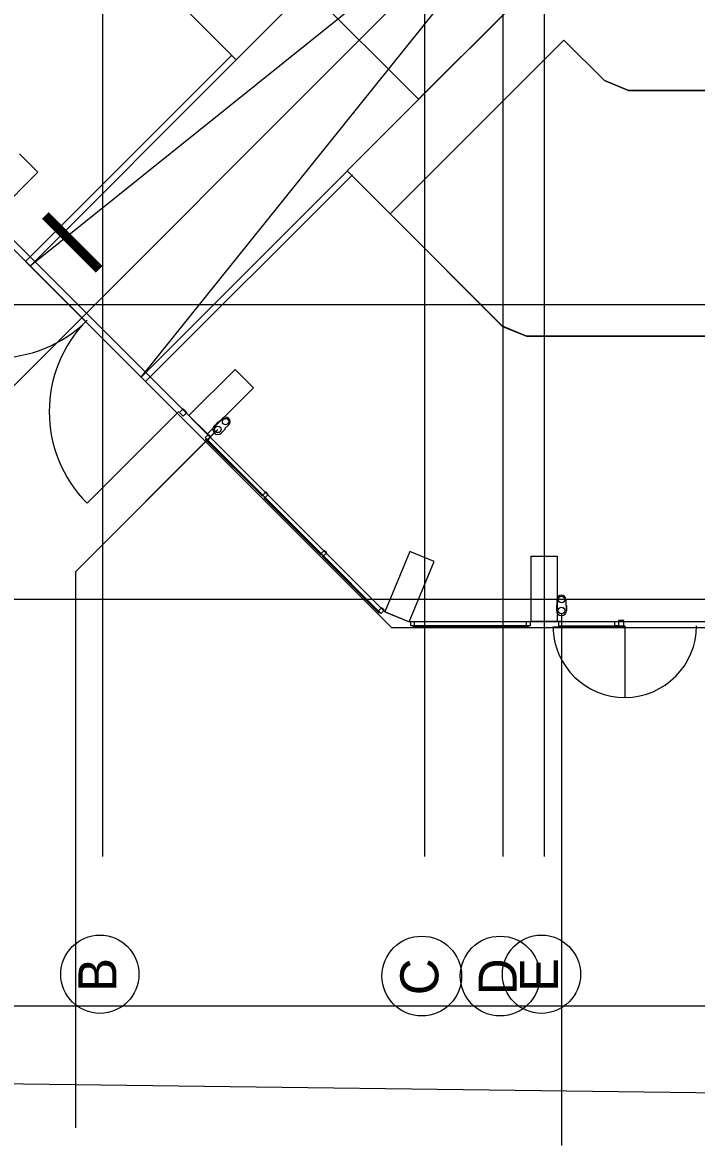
# Model space of a CAD drawing. Extents: x -264031 to -263588, y -1242281 to -1242059.
# Drawn here: x -263903.46 to -263887.96, y -1242253.35 to -1242227.54 of the extents above; entities that cross this region are included whole.
import ezdxf

# ---------------------------------------------------------------- set-up
doc = ezdxf.new("R2010")
doc.units = 0
for name, color, linetype in [('HESCON_OSI_STAVBY_KFA', 7, 'Continuous'), ('KFA_2D_SITUACIA_DSP', 7, 'Continuous'), ('KFA_JESTV_IS_DSP_-_KANAL_SPLASK', 7, 'Continuous')]:
    doc.layers.add(name, color=color, linetype=linetype)

msp = doc.modelspace()

# ---------------------------------------------------------------- linework, layer by layer
at = {"layer": 'HESCON_OSI_STAVBY_KFA'}
for p, q in [((-263901.618, -1242083.237), (-263901.618, -1242246.707)), ((-263894.218, -1242083.237), (-263894.218, -1242246.707)), ((-263892.418, -1242083.237), (-263892.418, -1242246.707)), ((-263891.468, -1242083.237), (-263891.468, -1242246.707)), ((-263792.653, -1242234.032), (-263911.523, -1242234.032)), ((-263792.653, -1242240.807), (-263911.523, -1242240.807))]:
    msp.add_line(p, q, dxfattribs=at)
for centre, radius in [((-263901.678, -1242249.416), 0.899), ((-263894.278, -1242249.457), 0.916), ((-263892.478, -1242249.457), 0.916), ((-263891.528, -1242249.416), 0.899)]:
    msp.add_circle(centre, radius, dxfattribs=at)
at = {"layer": 'KFA_2D_SITUACIA_DSP'}
for p, q in [((-263889.023, -1242221.253), (-263906.365, -1242238.596)), ((-263908.663, -1242227.55), (-263895.135, -1242241.078)), ((-263895.005, -1242231.945), (-263891.01, -1242227.95)), ((-263891.01, -1242227.95), (-263890.082, -1242228.878)), ((-263890.082, -1242228.878), (-263889.528, -1242229.107)), ((-263889.528, -1242229.107), (-263874.98, -1242229.107)), ((-263903.101, -1242230.985), (-263903.526, -1242230.561)), ((-263904.162, -1242232.046), (-263903.101, -1242230.985)), ((-263892.422, -1242234.528), (-263895.005, -1242231.945)), ((-263891.868, -1242234.757), (-263892.422, -1242234.528)), ((-263874.98, -1242234.757), (-263891.868, -1242234.757)), ((-263899.631, -1242236.576), (-263898.571, -1242235.516)), ((-263898.571, -1242235.516), (-263898.147, -1242235.94)), ((-263898.147, -1242235.94), (-263899.207, -1242237.001)), ((-263899.866, -1242236.488), (-263901.97, -1242238.592)), ((-263899.849, -1242236.506), (-263899.764, -1242236.421)), ((-263899.764, -1242236.591), (-263899.849, -1242236.506)), ((-263899.764, -1242236.421), (-263899.679, -1242236.506)), ((-263899.679, -1242236.506), (-263899.764, -1242236.591)), ((-263899.207, -1242237.001), (-263899.631, -1242236.576)), ((-263898.969, -1242236.733), (-263899.047, -1242236.812)), ((-263898.949, -1242236.733), (-263898.969, -1242236.733)), ((-263898.861, -1242236.645), (-263898.949, -1242236.733)), ((-263898.715, -1242236.791), (-263898.804, -1242236.879)), ((-263898.965, -1242236.895), (-263902.238, -1242240.168)), ((-263899.018, -1242236.948), (-263902.238, -1242240.168)), ((-263899.185, -1242237.014), (-263899.255, -1242237.084)), ((-263899.255, -1242237.084), (-263899.227, -1242237.113)), ((-263899.232, -1242237.108), (-263899.25, -1242237.125)), ((-263897.924, -1242238.416), (-263899.232, -1242237.108)), ((-263899.227, -1242237.113), (-263899.199, -1242237.141)), ((-263899.199, -1242237.141), (-263899.128, -1242237.07)), ((-263899.128, -1242237.07), (-263899.185, -1242237.014)), ((-263898.804, -1242236.899), (-263898.882, -1242236.977)), ((-263898.882, -1242236.977), (-263898.804, -1242236.899)), ((-263898.804, -1242236.879), (-263898.804, -1242236.899)), ((-263899.25, -1242237.125), (-263897.942, -1242238.434)), ((-263897.865, -1242238.333), (-263897.936, -1242238.404)), ((-263897.936, -1242238.404), (-263897.908, -1242238.432)), ((-263897.88, -1242238.46), (-263897.809, -1242238.389)), ((-263897.809, -1242238.389), (-263897.865, -1242238.333)), ((-263897.942, -1242238.434), (-263897.924, -1242238.416)), ((-263897.908, -1242238.432), (-263897.88, -1242238.46)), ((-263897.888, -1242238.452), (-263897.906, -1242238.469)), ((-263897.906, -1242238.469), (-263896.598, -1242239.778)), ((-263896.58, -1242239.76), (-263897.888, -1242238.452)), ((-263896.522, -1242239.677), (-263896.592, -1242239.748)), ((-263896.465, -1242239.733), (-263896.522, -1242239.677)), ((-263894.551, -1242239.702), (-263895.125, -1242241.088)), ((-263893.997, -1242239.932), (-263894.551, -1242239.702)), ((-263896.598, -1242239.778), (-263896.58, -1242239.76)), ((-263896.592, -1242239.748), (-263896.564, -1242239.776)), ((-263896.566, -1242239.809), (-263896.548, -1242239.792)), ((-263895.258, -1242241.118), (-263896.566, -1242239.809)), ((-263896.564, -1242239.776), (-263896.536, -1242239.804)), ((-263896.548, -1242239.792), (-263895.24, -1242241.1)), ((-263896.536, -1242239.804), (-263896.465, -1242239.733)), ((-263894.571, -1242241.318), (-263893.997, -1242239.932)), ((-263891.768, -1242241.312), (-263891.768, -1242239.812)), ((-263891.768, -1242239.812), (-263891.168, -1242239.812)), ((-263891.168, -1242239.812), (-263891.168, -1242241.312)), ((-263902.238, -1242240.168), (-263902.238, -1242252.949)), ((-263891.171, -1242240.932), (-263891.185, -1242240.946)), ((-263891.185, -1242240.946), (-263891.185, -1242241.057)), ((-263891.171, -1242240.807), (-263891.171, -1242240.932)), ((-263890.965, -1242240.807), (-263890.965, -1242240.932)), ((-263890.965, -1242240.932), (-263890.951, -1242240.946)), ((-263890.951, -1242241.057), (-263890.951, -1242240.946)), ((-263890.951, -1242240.946), (-263890.951, -1242241.057)), ((-263895.202, -1242240.996), (-263895.273, -1242241.067)), ((-263895.273, -1242241.067), (-263895.245, -1242241.095)), ((-263895.24, -1242241.1), (-263895.258, -1242241.118)), ((-263895.245, -1242241.095), (-263895.216, -1242241.123)), ((-263895.216, -1242241.123), (-263895.146, -1242241.053)), ((-263895.146, -1242241.053), (-263895.202, -1242240.996)), ((-263895.135, -1242241.078), (-263894.581, -1242241.307)), ((-263895.125, -1242241.088), (-263894.571, -1242241.318)), ((-263891.068, -1242241.132), (-263891.068, -1242253.353)), ((-263894.581, -1242241.307), (-263809.355, -1242241.307)), ((-263894.531, -1242241.407), (-263894.531, -1242241.307)), ((-263894.531, -1242241.307), (-263894.451, -1242241.307)), ((-263894.491, -1242241.407), (-263894.531, -1242241.407)), ((-263894.451, -1242241.407), (-263894.491, -1242241.407)), ((-263891.828, -1242241.407), (-263894.478, -1242241.407)), ((-263894.478, -1242241.407), (-263894.478, -1242241.432)), ((-263894.478, -1242241.432), (-263891.828, -1242241.432)), ((-263894.451, -1242241.307), (-263894.451, -1242241.407)), ((-263891.868, -1242241.407), (-263891.868, -1242241.307)), ((-263891.868, -1242241.307), (-263891.788, -1242241.307)), ((-263891.828, -1242241.407), (-263891.868, -1242241.407)), ((-263891.828, -1242241.432), (-263891.828, -1242241.407)), ((-263891.788, -1242241.407), (-263891.828, -1242241.407)), ((-263891.788, -1242241.307), (-263891.788, -1242241.407)), ((-263891.168, -1242241.312), (-263891.768, -1242241.312)), ((-263891.263, -1242241.432), (-263889.613, -1242241.432)), ((-263891.058, -1242241.307), (-263891.138, -1242241.307)), ((-263891.138, -1242241.307), (-263891.138, -1242241.407)), ((-263891.138, -1242241.407), (-263891.098, -1242241.407)), ((-263891.098, -1242241.432), (-263891.098, -1242241.407)), ((-263891.098, -1242241.407), (-263889.798, -1242241.407)), ((-263891.098, -1242241.407), (-263891.058, -1242241.407)), ((-263889.798, -1242241.432), (-263891.098, -1242241.432)), ((-263891.058, -1242241.407), (-263891.058, -1242241.307)), ((-263889.838, -1242241.407), (-263889.838, -1242241.307)), ((-263889.838, -1242241.307), (-263889.758, -1242241.307)), ((-263889.798, -1242241.407), (-263889.838, -1242241.407)), ((-263889.798, -1242241.407), (-263889.798, -1242241.432)), ((-263889.758, -1242241.407), (-263889.798, -1242241.407)), ((-263889.638, -1242241.287), (-263889.758, -1242241.287)), ((-263889.758, -1242241.287), (-263889.758, -1242241.407)), ((-263889.758, -1242241.307), (-263889.758, -1242241.407)), ((-263889.758, -1242241.407), (-263889.638, -1242241.407)), ((-263889.638, -1242241.407), (-263889.638, -1242241.287)), ((-263889.638, -1242241.407), (-263889.613, -1242241.407)), ((-263889.613, -1242241.407), (-263889.613, -1242243.057)), ((-263924.143, -1242250.14), (-263788.143, -1242250.14))]:
    msp.add_line(p, q, dxfattribs=at)
for points in [[(-263794.893, -1242227.382), (-263808.968, -1242241.457), (-263894.968, -1242241.457), (-263909.043, -1242227.382), (-263909.043, -1242196.333), (-263914.143, -1242196.333), (-263914.143, -1242132.433), (-263909.043, -1242132.433), (-263909.043, -1242101.382), (-263894.968, -1242087.307), (-263808.968, -1242087.307), (-263794.893, -1242101.382), (-263794.893, -1242227.382)], [(-263816.02, -1242224.432), (-263887.916, -1242224.432), (-263888.26, -1242224.088), (-263889.254, -1242226.488), (-263890.391, -1242225.351), (-263894.351, -1242229.311), (-263896.896, -1242226.765), (-263892.937, -1242222.806), (-263894.073, -1242221.669), (-263891.673, -1242220.675), (-263892.018, -1242220.33), (-263892.018, -1242181.432), (-263893.618, -1242181.432), (-263893.618, -1242147.332), (-263892.018, -1242147.332), (-263892.018, -1242108.434)], [(-263898.543, -1242228.407), (-263902.112, -1242224.837), (-263902.343, -1242224.282), (-263902.343, -1242203.332), (-263909.043, -1242203.332)], [(-263891.673, -1242220.675), (-263894.073, -1242221.669), (-263892.937, -1242222.806), (-263898.544, -1242228.407)], [(-263895.995, -1242230.956), (-263890.391, -1242225.352), (-263889.254, -1242226.488), (-263888.26, -1242224.088), (-263891.673, -1242220.675)], [(-263903.277, -1242233.148), (-263900.731, -1242235.694), (-263890.333, -1242222.748), (-263903.277, -1242233.148)], [(-263898.65, -1242228.301), (-263903.39, -1242233.035), (-263900.629, -1242235.796), (-263895.875, -1242231.049)], [(-263898.544, -1242228.407), (-263903.281, -1242233.144), (-263900.731, -1242235.694), (-263895.982, -1242230.943)], [(-263807.942, -1242230.956), (-263811.512, -1242234.526), (-263812.068, -1242234.757), (-263891.868, -1242234.757), (-263892.424, -1242234.526), (-263895.994, -1242230.956)]]:
    msp.add_lwpolyline(points, dxfattribs=at)
msp.add_lwpolyline([(-263891.01, -1242227.95), (-263895.005, -1242231.945), (-263892.422, -1242234.528), (-263891.868, -1242234.757), (-263874.98, -1242234.757), (-263874.98, -1242229.107), (-263889.528, -1242229.107), (-263890.082, -1242228.878)], close=True, dxfattribs=at)
for centre in [(-263898.965, -1242236.895), (-263898.788, -1242236.718), (-263891.068, -1242240.807), (-263891.068, -1242241.057)]:
    msp.add_circle(centre, 0.075, dxfattribs=at)
for centre, radius, start, end in [((-263904.074, -1242232.281), 2.975, 225.0001, 315.0001), ((-263899.866, -1242236.488), 2.975, 134.9999, 224.9999), ((-263898.965, -1242236.895), 0.117, 135, 315), ((-263898.788, -1242236.718), 0.103, 315, 135), ((-263891.068, -1242240.807), 0.103, 360, 180), ((-263891.068, -1242241.057), 0.117, 180, 360), ((-263889.613, -1242241.407), 1.65, 180.8682, 0)]:
    msp.add_arc(centre, radius, start, end, dxfattribs=at)
at = {"layer": 'KFA_JESTV_IS_DSP_-_KANAL_SPLASK'}
msp.add_line((-263877.504, -1242252.277), (-263922.041, -1242251.701), dxfattribs=at)

# ---------------------------------------------------------------- texts
at = {"layer": 'HESCON_OSI_STAVBY_KFA'}
for s, p in [('B', (-263901.297, -1242249.824)), ('C', (-263893.897, -1242249.898)), ('D', (-263892.097, -1242249.898)), ('E', (-263891.147, -1242249.824))]:
    msp.add_text(s, height=0.875, rotation=90, dxfattribs=at).set_placement(p)
at = {"layer": 'KFA_2D_SITUACIA_DSP'}
msp.add_text('I', height=1.75, rotation=45.0119, dxfattribs=at).set_placement((-263901.924, -1242233.448))

doc.saveas('drawing.dxf')
